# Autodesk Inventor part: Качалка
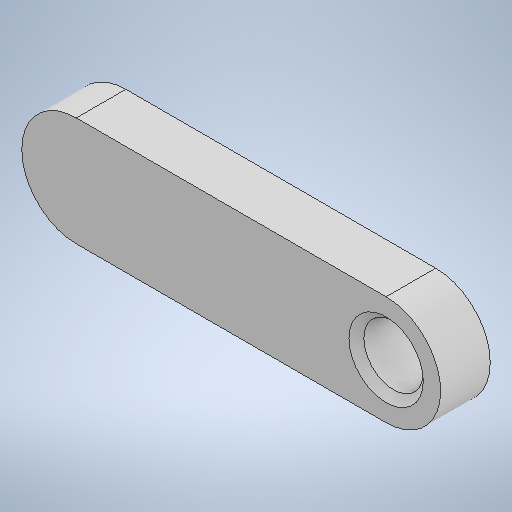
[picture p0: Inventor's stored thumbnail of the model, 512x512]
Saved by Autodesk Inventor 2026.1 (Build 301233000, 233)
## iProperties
Created: 2026-02
Part Number: Качалка
Material: Типовые
Document SubType Name: Modeling
Designer: Yury Melnikov
Density: 1 g/cm^3
Appearance: По умолчанию
Author: Yury Melnikov
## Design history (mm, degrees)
sketch "Эскиз1"
  geometry: L1 (0, 0)-(-25, 0); L2 (0, 4.4)-(-25, 4.4); L3 (-25, -4.4)-(0, -4.4); C1 r 2.4 at (0, 0); A1 r 4.4 centre (0, 0) between (0, -4.4) and (0, 4.4); A2 r 4.4 centre (-25, 0) between (-25, 4.4) and (-25, -4.4); 2 further points
  constraints: 8 end point, 4 point on circle, 4 tangent, 3 centre point, 1 coincident, 1 horizontal, 1 midpoint, 1 parallel
  dimensions: "d0" = 4.8 diameter of C1; "d1" = 25 distance of L1.start L1.end; "d2" = 2 radial gap between concentric circles of A1 C1
extrude "Выдавливание1" new body sketch "Эскиз1" distance "d3" = 4; taper "d4" = 0 deg
chamfer "Фаска1" distance "d5" = 0.6; stored, may be unused: second distance "d6" = 2, angle "d7" = 45 deg
node "Твердое тело1"
